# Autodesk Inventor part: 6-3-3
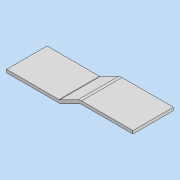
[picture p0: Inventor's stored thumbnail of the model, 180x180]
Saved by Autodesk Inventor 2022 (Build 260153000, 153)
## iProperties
Created: 2021-07
Part Number: 6-3-3
Material: 一般
Document SubType Name: Modeling
Designer: DesignLab
Density: 1 g/cm^3
Appearance: 既定
Author: DesignLab
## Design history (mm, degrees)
sketch "スケッチ1"
  geometry: L1 (25, 0)-(-28, 0); L2 (-28, 0)-(-48, 10); L3 (-48, 10)-(-100, 10); 1 further point
  constraints: 6 end point, 1 horizontal, 1 parallel, 1 point on line
  dimensions: "d0" = 25 distance of point (0, 0) L1.start; "d1" = 100 horizontal distance of L3.end point (0, 0); "d2" = 10 distance between parallel lines of L1 L3; "d3" = 28 distance of L1.end point (0, 0); "d4" = 20 horizontal distance of L1.end L2.end
feature "押し出しサーフェス1" sketch "スケッチ1" dims "d5" = 40, "d6" = 0
fillet "フィレット1" dims "d7" = 5
feature "厚み1" dims "d8" = 3
node "ソリッド1"
body "Srf1"
